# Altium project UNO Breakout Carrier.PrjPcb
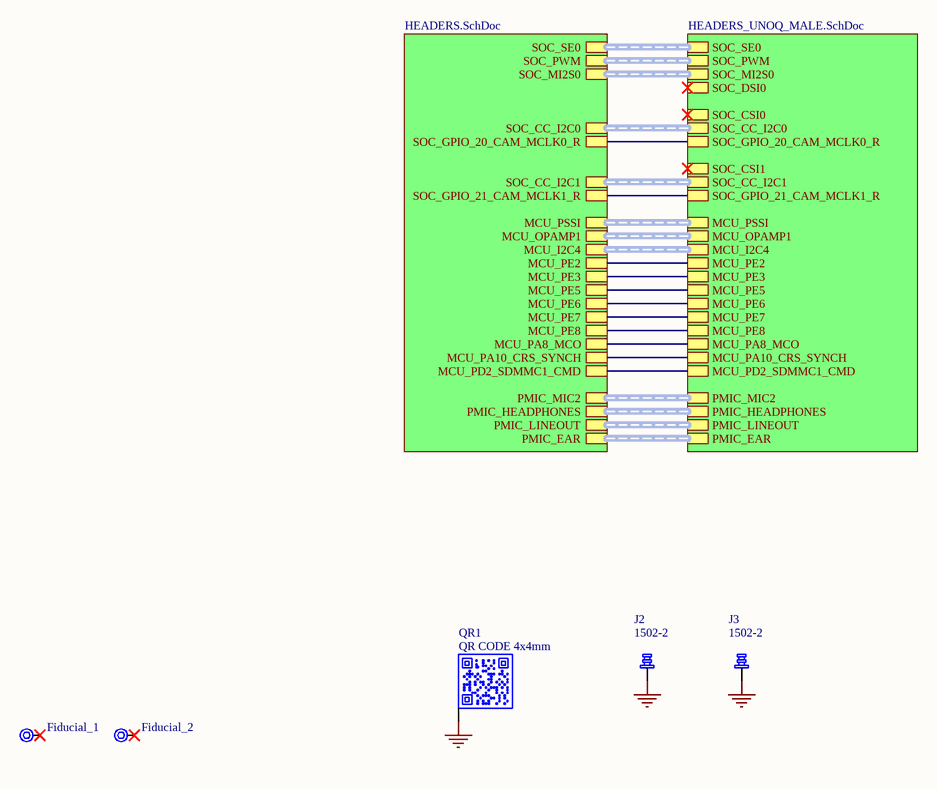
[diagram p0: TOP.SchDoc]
ADDITIONAL CODENAME: PANEN; ASSEMBLY_BGA: _; ASSEMBLY_PRESSFIT: _; ASSEMBLY_SMD: X; ASSEMBLY_THT: X; BOARD_CODENAME: UNO Breakout Carrier; BOARD_INFO_AUTHOR: Jonny Favaro; BOARD_INFO_AUTHOR_REV: Silvio Navaretti; BOARD_INFO_Er: _; BOARD_INFO_FLEX: _; BOARD_INFO_FR4: X; BOARD_INFO_FR4_HTG: _; BOARD_INFO_IPC1: _; BOARD_INFO_IPC2: X; BOARD_INFO_IPC3: _; BOARD_INFO_IPC_NA: _; BOARD_INFO_NUMBER_OF_LAYERS: 4; BOARD_INFO_PCB_SIZE: 107.6x53.34mm; BOARD_INFO_POLYMIDE: _; BOARD_INFO_RIGID: X; BOARD_INFO_RIGID/FLEX: _; BOARD_INFO_TBD: _; BOARD_INFO_THICKNESS: 1.6mm; DRILLS_BLIND: _; DRILLS_BURIED: _; DRILLS_COPPER_FILLING: _; DRILLS_FULL: X; DRILLS_LASER: _; DRILLS_PRESSFIT: _; DRILLS_RESIN_FILLING: _; DRILLS_SLOT: _; DRILLS_SOLDER_FILLING: X; FINISH_ADJUSTMENTS: _; FINISH_EDGE_PLATING: _; FINISH_ENIG: _; FINISH_HAL: _; FINISH_HAL_LF: X; FINISH_NI/AU: _; FINISH_SILK_BOTTOM: X; FINISH_SILK_COLOR: WHITE; FINISH_SILK_TOP: X; FINISH_SN/PB: _; FINISH_SOLDERMASK_BOTTOM: X; FINISH_SOLDERMASK_COLOR: BLUE; FINISH_SOLDERMASK_PEELABLE_BOTTOM: _; FINISH_SOLDERMASK_PEELABLE_COLOR: _; FINISH_SOLDERMASK_PEELABLE_TOP: _; FINISH_SOLDERMASK_TOP: X; FINISH_TABS: _; FINISH_TBD: _; INSULATION_MIN_INNER: 0.127mm; INSULATION_MIN_OUTER: 0.127mm; PANEL_MILLING: X; PANEL_NOT_REQUESTED: _; PANEL_NUMBER_OF_FIGURES: 5; PANEL_PROVIDED: X; PANEL_REQUESTED: _; PANEL_SCORING: X; PANEL_SIZE: 316.7x125.6mm; PANEL_TABS: _; SKU: ASX00085; TRACK_MIN_WIDTH_INNER: 0.127mm; TRACK_MIN_WIDTH_OUTER: 0.127mm; Version: V0.4; VIA_1: _; VIA_1_HOLE_MM: _; VIA_1_PAD_MM: _; VIA_2: _; VIA_2_HOLE_MM: _; VIA_2_PAD_MM: _; VIA_3: _; VIA_3_HOLE_MM: _; VIA_3_PAD_MM: _; VIA_4: _; VIA_4_HOLE_MM: _; VIA_4_PAD_MM: _; VIA_5: _; VIA_5_HOLE_MM: _; VIA_5_PAD_MM: _; VIA_THROUGH: X; VIA_THROUGH_HOLE_MM: 0.3; VIA_THROUGH_PAD_MM: 0.6
3 sheets, 10 parts. Net scope: hierarchical (ports join the sheet entries above them; power ports are global).
Board files: PCB.PcbDoc, PANEL.PcbDoc
Sheets:
  TOP.SchDoc
    U_HEADERS_IMOLA_MALE = HEADERS_UNOQ_MALE.SchDoc
    U_HEADERS = HEADERS.SchDoc

## Sheet TOP.SchDoc: TOP
size A4; Author: Jonny Favaro; CompanyName: ARDUINO SRL; Organization: ARDUINO SRL; SheetNumber: 1; SheetTotal: 3; RevAuthor: Jonny Favaro

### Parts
Fiducial_1  Fiducial mark 1mm with 2mm solder  [Fiducial mark 1mm with circle-Footprint-1]  (value not drawn)  (no BOM)
Fiducial_2  Fiducial mark 1mm with 2mm solder  [Fiducial mark 1mm with circle-Footprint-1]  (value not drawn)  (no BOM)
J2  1502-2  [1502-2]
J3  1502-2  [1502-2]
QR1  QR CODE 4x4mm  [QR CODE 4x4mm]  (no BOM)

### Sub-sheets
U_HEADERS = HEADERS.SchDoc: SOC_SE0, SOC_PWM, SOC_MI2S0, SOC_CC_I2C0, SOC_GPIO_20_CAM_MCLK0_R, SOC_CC_I2C1, SOC_GPIO_21_CAM_MCLK1_R, MCU_PSSI, MCU_OPAMP1, MCU_I2C4, MCU_PE2, MCU_PE3, MCU_PE5, MCU_PE6, MCU_PE7, MCU_PE8, MCU_PA8_MCO, MCU_PA10_CRS_SYNCH, MCU_PD2_SDMMC1_CMD, PMIC_MIC2, PMIC_HEADPHONES, PMIC_LINEOUT, PMIC_EAR
U_HEADERS_IMOLA_MALE = HEADERS_UNOQ_MALE.SchDoc: SOC_CSI0 (harness IMOLA_CSI), SOC_GPIO_20_CAM_MCLK0_R, SOC_CC_I2C1 (harness I2C), SOC_CSI1 (harness IMOLA_CSI), SOC_GPIO_21_CAM_MCLK1_R, SOC_CC_I2C0 (harness I2C), SOC_DSI0 (harness IMOLA_DSI), MCU_PSSI (harness PSSI_MCU), PMIC_MIC2 (harness MIC), MCU_PD2_SDMMC1_CMD, MCU_I2C4 (harness I2C), MCU_OPAMP1 (harness MCU_OPAMP), PMIC_LINEOUT (harness LINEOUT), PMIC_HEADPHONES (harness HEADPHONES), SOC_PWM (harness SOC_PWM), SOC_SE0 (harness SOC_GPIO), MCU_PA10_CRS_SYNCH, MCU_PA8_MCO, MCU_PE7, MCU_PE8, PMIC_EAR (harness EAT), SOC_MI2S0 (harness SOC_I2S), MCU_PE2, MCU_PE3, MCU_PE5, MCU_PE6

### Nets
GND: J2.1 J3.1 QR1.PAD
NetJ14_2: sheet U_HEADERS_IMOLA_MALE/SOC_GPIO_20_CAM_MCLK0_R, sheet U_HEADERS/SOC_GPIO_20_CAM_MCLK0_R
NetJ14_4: sheet U_HEADERS_IMOLA_MALE/SOC_GPIO_21_CAM_MCLK1_R, sheet U_HEADERS/SOC_GPIO_21_CAM_MCLK1_R
NetJ15_2: sheet U_HEADERS_IMOLA_MALE/MCU_PD2_SDMMC1_CMD, sheet U_HEADERS/MCU_PD2_SDMMC1_CMD
NetJ15_4: sheet U_HEADERS_IMOLA_MALE/MCU_PE2, sheet U_HEADERS/MCU_PE2
NetJ15_6: sheet U_HEADERS_IMOLA_MALE/MCU_PE3, sheet U_HEADERS/MCU_PE3
NetJ15_8: sheet U_HEADERS_IMOLA_MALE/MCU_PE5, sheet U_HEADERS/MCU_PE5
NetJ15_10: sheet U_HEADERS_IMOLA_MALE/MCU_PE6, sheet U_HEADERS/MCU_PE6
NetJ15_12: sheet U_HEADERS_IMOLA_MALE/MCU_PE7, sheet U_HEADERS/MCU_PE7
NetJ15_14: sheet U_HEADERS_IMOLA_MALE/MCU_PE8, sheet U_HEADERS/MCU_PE8
NetJ15_26: sheet U_HEADERS_IMOLA_MALE/MCU_PA8_MCO, sheet U_HEADERS/MCU_PA8_MCO
NetJ15_28: sheet U_HEADERS_IMOLA_MALE/MCU_PA10_CRS_SYNCH, sheet U_HEADERS/MCU_PA10_CRS_SYNCH

Not connected (* = marked no-connect by the designer): Fiducial_1 1*; Fiducial_2 1*

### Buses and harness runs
harness sheet U_HEADERS/MCU_I2C4 = sheet U_HEADERS_IMOLA_MALE/MCU_I2C4
harness sheet U_HEADERS/MCU_OPAMP1 = sheet U_HEADERS_IMOLA_MALE/MCU_OPAMP1
harness sheet U_HEADERS/MCU_PSSI = sheet U_HEADERS_IMOLA_MALE/MCU_PSSI
harness sheet U_HEADERS/PMIC_EAR = sheet U_HEADERS_IMOLA_MALE/PMIC_EAR
harness sheet U_HEADERS/PMIC_HEADPHONES = sheet U_HEADERS_IMOLA_MALE/PMIC_HEADPHONES
harness sheet U_HEADERS/PMIC_LINEOUT = sheet U_HEADERS_IMOLA_MALE/PMIC_LINEOUT
harness sheet U_HEADERS/PMIC_MIC2 = sheet U_HEADERS_IMOLA_MALE/PMIC_MIC2
harness sheet U_HEADERS/SOC_CC_I2C0 = sheet U_HEADERS_IMOLA_MALE/SOC_CC_I2C0
harness sheet U_HEADERS/SOC_CC_I2C1 = sheet U_HEADERS_IMOLA_MALE/SOC_CC_I2C1
harness sheet U_HEADERS/SOC_MI2S0 = sheet U_HEADERS_IMOLA_MALE/SOC_MI2S0
harness sheet U_HEADERS/SOC_PWM = sheet U_HEADERS_IMOLA_MALE/SOC_PWM
harness sheet U_HEADERS/SOC_SE0 = sheet U_HEADERS_IMOLA_MALE/SOC_SE0

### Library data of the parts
Fiducial_1 Fiducial_2 = UT0024-A.6
J2 J3 = J0379-A.2: Turret Connector TH 5,56mm lenght; Manufacturer: Keystone Electronics; Code Arduino: J0379
QR1 = QR-0001-A.5: QR CODE 4x4mm on layer 34 (This is not a component); Code Arduino: QRCODE_4x4mm

## Sheet HEADERS_UNOQ_MALE.SchDoc: HEADERS UNO Q MALE
size A3; Author: Jonny Favaro; CompanyName: Arduino SRL; Organization: Arduino SRL; SheetNumber: 2; SheetTotal: 3; RevAuthor: Jonny Favaro
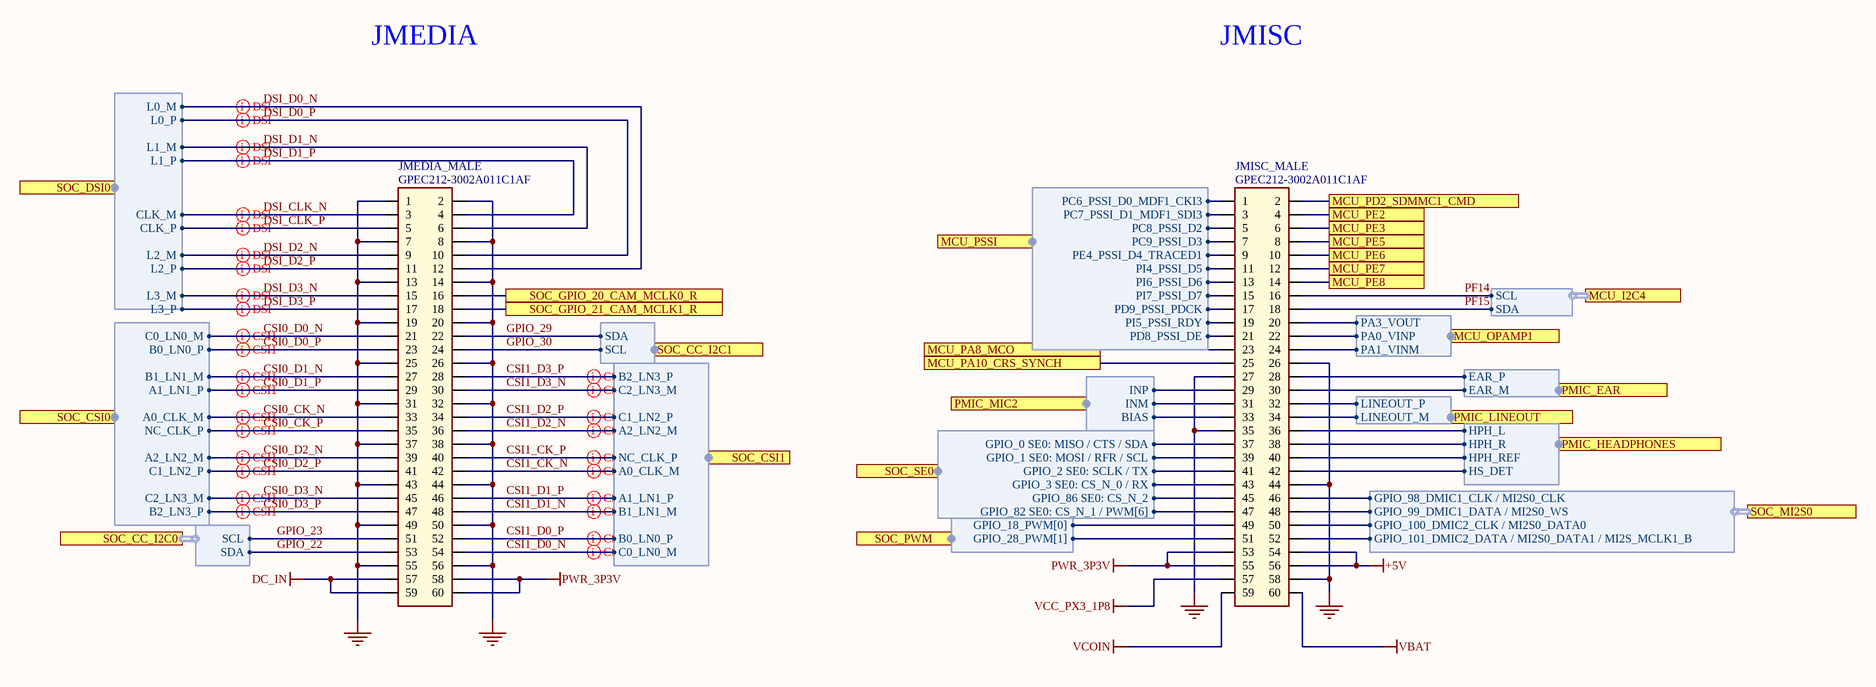
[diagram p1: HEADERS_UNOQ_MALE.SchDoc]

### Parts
JMEDIA_MALE  GPEC212-3002A011C1AF  [GPEC212-3002A011C1AF]
JMISC_MALE  GPEC212-3002A011C1AF  [GPEC212-3002A011C1AF]

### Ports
MCU_I2C4 (harness I2C), MCU_OPAMP1 (harness MCU_OPAMP), MCU_PA8_MCO, MCU_PA10_CRS_SYNCH, MCU_PD2_SDMMC1_CMD, MCU_PE2, MCU_PE3, MCU_PE5, MCU_PE6, MCU_PE7, MCU_PE8, MCU_PSSI (harness PSSI_MCU), PMIC_EAR (harness EAT), PMIC_HEADPHONES (harness HEADPHONES), PMIC_LINEOUT (harness LINEOUT), PMIC_MIC2 (harness MIC), SOC_CC_I2C0 (harness I2C), SOC_CC_I2C1 (harness I2C), SOC_CSI0 (harness IMOLA_CSI), SOC_CSI1 (harness IMOLA_CSI), SOC_DSI0 (harness IMOLA_DSI), SOC_GPIO_20_CAM_MCLK0_R, SOC_GPIO_21_CAM_MCLK1_R, SOC_MI2S0 (harness SOC_I2S), SOC_PWM (harness SOC_PWM), SOC_SE0 (harness SOC_GPIO)

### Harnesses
IMOLA_DSI: L1_P, L1_M, L3_P, L3_M, CLK_P, CLK_M, L0_P, L0_M, L2_P, L2_M
I2C: SDA, SCL
IMOLA_CSI: C2_LN3_M, A2_LN2_M, C1_LN2_P, C0_LN0_M, B0_LN0_P, A0_CLK_M, NC_CLK_P, B1_LN1_M, A1_LN1_P, B2_LN3_P
PSSI_MCU: PC6_PSSI_D0_MDF1_CKI3, PC7_PSSI_D1_MDF1_SDI3, PC8_PSSI_D2, PC9_PSSI_D3, PE4_PSSI_D4_TRACED1, PI4_PSSI_D5, PI6_PSSI_D6, PI7_PSSI_D7, PD9_PSSI_PDCK, PI5_PSSI_RDY, PD8_PSSI_DE
MCU_OPAMP: PA3_VOUT, PA0_VINP, PA1_VINM
EAT: EAR_P, EAR_M
MIC: INP, INM, BIAS
LINEOUT: LINEOUT_P, LINEOUT_M
HEADPHONES: HPH_L, HPH_R, HPH_REF, HS_DET
SOC_GPIO: GPIO_0 SE0: MISO / CTS / SDA, GPIO_1 SE0: MOSI / RFR / SCL, GPIO_2 SE0: SCLK / TX, GPIO_3 SE0: CS_N_0 / RX, GPIO_86 SE0: CS_N_2, GPIO_82 SE0: CS_N_1 / PWM[6]
SOC_I2S: GPIO_98_DMIC1_CLK / MI2S0_CLK, GPIO_99_DMIC1_DATA / MI2S0_WS, GPIO_100_DMIC2_CLK / MI2S0_DATA0, GPIO_101_DMIC2_DATA / MI2S0_DATA1 / MI2S_MCLK1_B
SOC_PWM: GPIO_18_PWM[0], GPIO_28_PWM[1]

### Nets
+5V: JMISC_MALE.54 JMISC_MALE.56
DC_IN: JMEDIA_MALE.57 JMEDIA_MALE.59
GND: JMEDIA_MALE.1 JMEDIA_MALE.2 JMEDIA_MALE.7 JMEDIA_MALE.8 JMEDIA_MALE.13 JMEDIA_MALE.14 JMEDIA_MALE.19 JMEDIA_MALE.20 JMEDIA_MALE.25 JMEDIA_MALE.26 JMEDIA_MALE.31 JMEDIA_MALE.32 JMEDIA_MALE.37 JMEDIA_MALE.38 JMEDIA_MALE.43 JMEDIA_MALE.44 JMEDIA_MALE.49 JMEDIA_MALE.50 JMEDIA_MALE.55 JMEDIA_MALE.56 JMISC_MALE.26 JMISC_MALE.27 JMISC_MALE.35 JMISC_MALE.44 JMISC_MALE.58
PWR_3P3V: JMEDIA_MALE.58 JMEDIA_MALE.60 JMISC_MALE.53 JMISC_MALE.55
VBAT: JMISC_MALE.60
VCC_PX3_1P8: JMISC_MALE.57
VCOIN: JMISC_MALE.59
CSI0_CK_N: JMEDIA_MALE.33 ; port SOC_CSI0.A0_CLK_M
CSI0_CK_P: JMEDIA_MALE.35 ; port SOC_CSI0.NC_CLK_P
CSI0_D0_N: JMEDIA_MALE.21 ; port SOC_CSI0.C0_LN0_M
CSI0_D0_P: JMEDIA_MALE.23 ; port SOC_CSI0.B0_LN0_P
CSI0_D1_N: JMEDIA_MALE.27 ; port SOC_CSI0.B1_LN1_M
CSI0_D1_P: JMEDIA_MALE.29 ; port SOC_CSI0.A1_LN1_P
CSI0_D2_N: JMEDIA_MALE.39 ; port SOC_CSI0.A2_LN2_M
CSI0_D2_P: JMEDIA_MALE.41 ; port SOC_CSI0.C1_LN2_P
CSI0_D3_N: JMEDIA_MALE.45 ; port SOC_CSI0.C2_LN3_M
CSI0_D3_P: JMEDIA_MALE.47 ; port SOC_CSI0.B2_LN3_P
CSI1_CK_N: JMEDIA_MALE.42 ; port SOC_CSI1.A0_CLK_M
CSI1_CK_P: JMEDIA_MALE.40 ; port SOC_CSI1.NC_CLK_P
CSI1_D0_N: JMEDIA_MALE.54 ; port SOC_CSI1.C0_LN0_M
CSI1_D0_P: JMEDIA_MALE.52 ; port SOC_CSI1.B0_LN0_P
CSI1_D1_N: JMEDIA_MALE.48 ; port SOC_CSI1.B1_LN1_M
CSI1_D1_P: JMEDIA_MALE.46 ; port SOC_CSI1.A1_LN1_P
CSI1_D2_N: JMEDIA_MALE.36 ; port SOC_CSI1.A2_LN2_M
CSI1_D2_P: JMEDIA_MALE.34 ; port SOC_CSI1.C1_LN2_P
CSI1_D3_N: JMEDIA_MALE.30 ; port SOC_CSI1.C2_LN3_M
CSI1_D3_P: JMEDIA_MALE.28 ; port SOC_CSI1.B2_LN3_P
DSI_CLK_N: JMEDIA_MALE.3 ; port SOC_DSI0.CLK_M
DSI_CLK_P: JMEDIA_MALE.5 ; port SOC_DSI0.CLK_P
DSI_D0_N: JMEDIA_MALE.12 ; port SOC_DSI0.L0_M
DSI_D0_P: JMEDIA_MALE.10 ; port SOC_DSI0.L0_P
DSI_D1_N: JMEDIA_MALE.6 ; port SOC_DSI0.L1_M
DSI_D1_P: JMEDIA_MALE.4 ; port SOC_DSI0.L1_P
DSI_D2_N: JMEDIA_MALE.9 ; port SOC_DSI0.L2_M
DSI_D2_P: JMEDIA_MALE.11 ; port SOC_DSI0.L2_P
DSI_D3_N: JMEDIA_MALE.15 ; port SOC_DSI0.L3_M
DSI_D3_P: JMEDIA_MALE.17 ; port SOC_DSI0.L3_P
GPIO_22: JMEDIA_MALE.53 ; port SOC_CC_I2C0.SDA
GPIO_23: JMEDIA_MALE.51 ; port SOC_CC_I2C0.SCL
GPIO_29: JMEDIA_MALE.22 ; port SOC_CC_I2C1.SDA
GPIO_30: JMEDIA_MALE.24 ; port SOC_CC_I2C1.SCL
PF14: JMISC_MALE.16 ; port MCU_I2C4.SCL
PF15: JMISC_MALE.18 ; port MCU_I2C4.SDA
NetJ14_2: JMEDIA_MALE.16 ; port SOC_GPIO_20_CAM_MCLK0_R
NetJ14_4: JMEDIA_MALE.18 ; port SOC_GPIO_21_CAM_MCLK1_R
NetJ14_20: JMISC_MALE.29 ; port PMIC_MIC2.INP
NetJ14_22: JMISC_MALE.31 ; port PMIC_MIC2.INM
NetJ14_24: JMISC_MALE.33 ; port PMIC_MIC2.BIAS
NetJ14_27: JMISC_MALE.32 ; port PMIC_LINEOUT.LINEOUT_P
NetJ14_28: JMISC_MALE.28 ; port PMIC_EAR.EAR_P
NetJ14_29: JMISC_MALE.34 ; port PMIC_LINEOUT.LINEOUT_M
NetJ14_30: JMISC_MALE.30 ; port PMIC_EAR.EAR_M
NetJ14_34: JMISC_MALE.36 ; port PMIC_HEADPHONES.HPH_L
NetJ14_36: JMISC_MALE.38 ; port PMIC_HEADPHONES.HPH_R
NetJ14_38: JMISC_MALE.40 ; port PMIC_HEADPHONES.HPH_REF
NetJ14_40: JMISC_MALE.42 ; port PMIC_HEADPHONES.HS_DET
NetJ15_1: JMISC_MALE.1 ; port MCU_PSSI.PC6_PSSI_D0_MDF1_CKI3
NetJ15_2: JMISC_MALE.2 ; port MCU_PD2_SDMMC1_CMD
NetJ15_3: JMISC_MALE.3 ; port MCU_PSSI.PC7_PSSI_D1_MDF1_SDI3
NetJ15_4: JMISC_MALE.4 ; port MCU_PE2
NetJ15_5: JMISC_MALE.5 ; port MCU_PSSI.PC8_PSSI_D2
NetJ15_6: JMISC_MALE.6 ; port MCU_PE3
NetJ15_7: JMISC_MALE.7 ; port MCU_PSSI.PC9_PSSI_D3
NetJ15_8: JMISC_MALE.8 ; port MCU_PE5
NetJ15_9: JMISC_MALE.9 ; port MCU_PSSI.PE4_PSSI_D4_TRACED1
NetJ15_10: JMISC_MALE.10 ; port MCU_PE6
NetJ15_11: JMISC_MALE.11 ; port MCU_PSSI.PI4_PSSI_D5
NetJ15_12: JMISC_MALE.12 ; port MCU_PE7
NetJ15_13: JMISC_MALE.13 ; port MCU_PSSI.PI6_PSSI_D6
NetJ15_14: JMISC_MALE.14 ; port MCU_PE8
NetJ15_15: JMISC_MALE.15 ; port MCU_PSSI.PI7_PSSI_D7
NetJ15_17: JMISC_MALE.17 ; port MCU_PSSI.PD9_PSSI_PDCK
NetJ15_19: JMISC_MALE.19 ; port MCU_PSSI.PI5_PSSI_RDY
NetJ15_20: JMISC_MALE.20 ; port MCU_OPAMP1.PA3_VOUT
NetJ15_21: JMISC_MALE.21 ; port MCU_PSSI.PD8_PSSI_DE
NetJ15_22: JMISC_MALE.22 ; port MCU_OPAMP1.PA0_VINP
NetJ15_24: JMISC_MALE.24 ; port MCU_OPAMP1.PA1_VINM
NetJ15_25: JMISC_MALE.37 ; port SOC_SE0.GPIO_0 SE0: MISO / CTS / SDA
NetJ15_26: JMISC_MALE.23 ; port MCU_PA8_MCO
NetJ15_27: JMISC_MALE.39 ; port SOC_SE0.GPIO_1 SE0: MOSI / RFR / SCL
NetJ15_28: JMISC_MALE.25 ; port MCU_PA10_CRS_SYNCH
NetJ15_29: JMISC_MALE.41 ; port SOC_SE0.GPIO_2 SE0: SCLK / TX
NetJ15_31: JMISC_MALE.43 ; port SOC_SE0.GPIO_3 SE0: CS_N_0 / RX
NetJ15_32: JMISC_MALE.46 ; port SOC_MI2S0.GPIO_98_DMIC1_CLK / MI2S0_CLK
NetJ15_33: JMISC_MALE.45 ; port SOC_SE0.GPIO_86 SE0: CS_N_2
NetJ15_34: JMISC_MALE.48 ; port SOC_MI2S0.GPIO_99_DMIC1_DATA / MI2S0_WS
NetJ15_35: JMISC_MALE.47 ; port SOC_SE0.GPIO_82 SE0: CS_N_1 / PWM[6]
NetJ15_36: JMISC_MALE.50 ; port SOC_MI2S0.GPIO_100_DMIC2_CLK / MI2S0_DATA0
NetJ15_37: JMISC_MALE.49 ; port SOC_PWM.GPIO_18_PWM[0]
NetJ15_38: JMISC_MALE.52 ; port SOC_MI2S0.GPIO_101_DMIC2_DATA / MI2S0_DATA1 / MI2S_MCLK1_B
NetJ15_39: JMISC_MALE.51 ; port SOC_PWM.GPIO_28_PWM[1]

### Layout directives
differential pair; differential pair class DSI; net class IMPEDANCE_100R: DSI_CLK_N, DSI_CLK_P, DSI_D0_N, DSI_D0_P, DSI_D1_N, DSI_D1_P, DSI_D2_N, DSI_D2_P, DSI_D3_N, DSI_D3_P
differential pair; differential pair class CSI1; net class IMPEDANCE_100R: CSI0_CK_N, CSI0_CK_P, CSI0_D0_N, CSI0_D0_P, CSI0_D1_N, CSI0_D1_P, CSI0_D2_N, CSI0_D2_P, CSI0_D3_N, CSI0_D3_P
differential pair; differential pair class CSI0; net class IMPEDANCE_100R: CSI1_CK_N, CSI1_CK_P, CSI1_D0_N, CSI1_D0_P, CSI1_D1_N, CSI1_D1_P, CSI1_D2_N, CSI1_D2_P, CSI1_D3_N, CSI1_D3_P

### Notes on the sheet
- JMEDIA
- JMISC

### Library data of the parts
JMEDIA_MALE JMISC_MALE = J0568-A.3: CONN HEADER MALE VERTICAL SMD 1.27mm 2x30 POS lead heigth 3.5mm; Manufacturer: Greenconn; Code Arduino: J0568

## Sheet HEADERS.SchDoc: HEADERS
size A4; Author: Jonny Favaro; CompanyName: Arduino srl; Organization: ARDUINO SRL; SheetNumber: 3; SheetTotal: 3; RevAuthor: Jonny Favaro
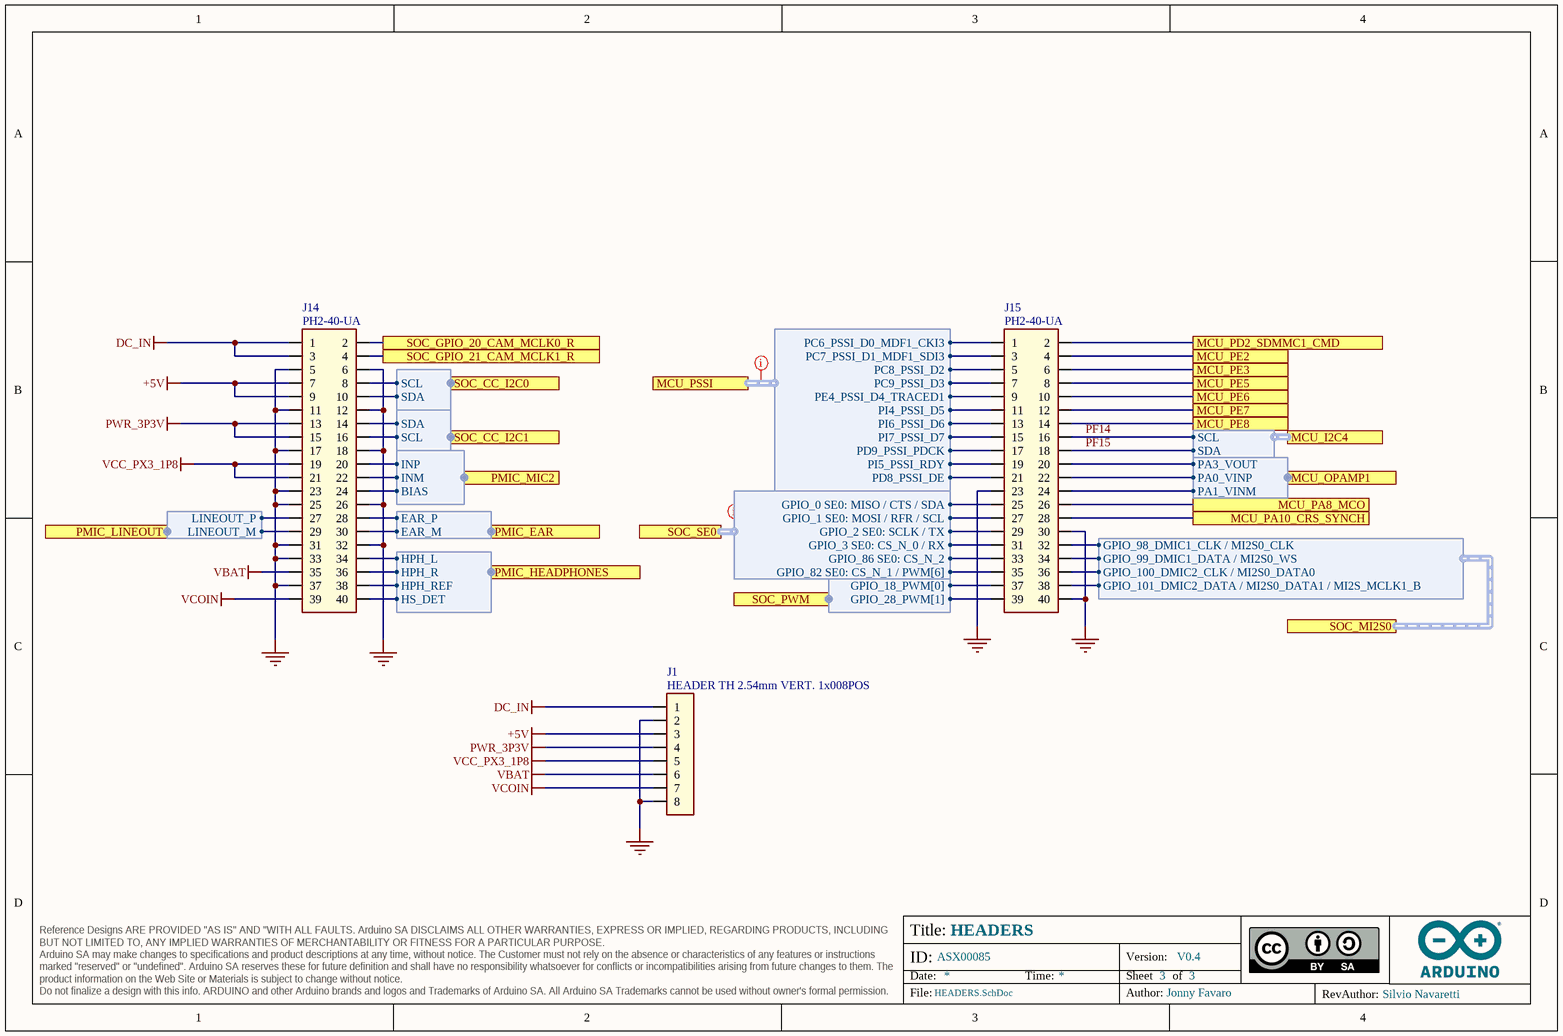
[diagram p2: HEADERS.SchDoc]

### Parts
J1  HEADER TH 2.54mm VERT. 1x008POS  [PIN HEADER 2.54mm VERT. 1x8POS]  (no BOM)
J14  PH2-40-UA  [PIN HEADER 2.54mm VERT. 2x20POS]
J15  PH2-40-UA  [PIN HEADER 2.54mm VERT. 2x20POS]

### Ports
MCU_I2C4 (harness I2C), MCU_OPAMP1 (harness MCU_OPAMP), MCU_PA8_MCO, MCU_PA10_CRS_SYNCH, MCU_PD2_SDMMC1_CMD, MCU_PE2, MCU_PE3, MCU_PE5, MCU_PE6, MCU_PE7, MCU_PE8, MCU_PSSI (harness PSSI_MCU), PMIC_EAR (harness EAT), PMIC_HEADPHONES (harness HEADPHONES), PMIC_LINEOUT (harness LINEOUT), PMIC_MIC2 (harness MIC), SOC_CC_I2C0 (harness I2C), SOC_CC_I2C1 (harness I2C), SOC_GPIO_20_CAM_MCLK0_R, SOC_GPIO_21_CAM_MCLK1_R, SOC_MI2S0 (harness SOC_I2S), SOC_PWM (harness SOC_PWM), SOC_SE0 (harness SOC_GPIO)

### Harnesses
SOC_GPIO: GPIO_0 SE0: MISO / CTS / SDA, GPIO_1 SE0: MOSI / RFR / SCL, GPIO_2 SE0: SCLK / TX, GPIO_3 SE0: CS_N_0 / RX, GPIO_86 SE0: CS_N_2, GPIO_82 SE0: CS_N_1 / PWM[6]
SOC_PWM: GPIO_18_PWM[0], GPIO_28_PWM[1]
I2C: SDA, SCL
MCU_OPAMP: PA3_VOUT, PA0_VINP, PA1_VINM
SOC_I2S: GPIO_98_DMIC1_CLK / MI2S0_CLK, GPIO_99_DMIC1_DATA / MI2S0_WS, GPIO_100_DMIC2_CLK / MI2S0_DATA0, GPIO_101_DMIC2_DATA / MI2S0_DATA1 / MI2S_MCLK1_B
PSSI_MCU: PC6_PSSI_D0_MDF1_CKI3, PC7_PSSI_D1_MDF1_SDI3, PC8_PSSI_D2, PC9_PSSI_D3, PE4_PSSI_D4_TRACED1, PI4_PSSI_D5, PI6_PSSI_D6, PI7_PSSI_D7, PD9_PSSI_PDCK, PI5_PSSI_RDY, PD8_PSSI_DE
HEADPHONES: HPH_L, HPH_R, HPH_REF, HS_DET
MIC: INP, INM, BIAS
EAT: EAR_P, EAR_M
LINEOUT: LINEOUT_P, LINEOUT_M

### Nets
+5V: J1.3 J14.7 J14.9
DC_IN: J1.1 J14.1 J14.3
GND: J1.2 J1.8 J14.5 J14.6 J14.11 J14.12 J14.17 J14.18 J14.23 J14.25 J14.26 J14.31 J14.32 J14.33 J14.37 J15.23 J15.30 J15.40
PWR_3P3V: J1.4 J14.13 J14.15
VBAT: J1.6 J14.35
VCC_PX3_1P8: J1.5 J14.19 J14.21
VCOIN: J1.7 J14.39
GPIO_22: J14.10 ; port SOC_CC_I2C0.SDA
GPIO_23: J14.8 ; port SOC_CC_I2C0.SCL
GPIO_29: J14.14 ; port SOC_CC_I2C1.SDA
GPIO_30: J14.16 ; port SOC_CC_I2C1.SCL
PF14: J15.16 ; port MCU_I2C4.SCL
PF15: J15.18 ; port MCU_I2C4.SDA
NetJ14_2: J14.2 ; port SOC_GPIO_20_CAM_MCLK0_R
NetJ14_4: J14.4 ; port SOC_GPIO_21_CAM_MCLK1_R
NetJ14_20: J14.20 ; port PMIC_MIC2.INP
NetJ14_22: J14.22 ; port PMIC_MIC2.INM
NetJ14_24: J14.24 ; port PMIC_MIC2.BIAS
NetJ14_27: J14.27 ; port PMIC_LINEOUT.LINEOUT_P
NetJ14_28: J14.28 ; port PMIC_EAR.EAR_P
NetJ14_29: J14.29 ; port PMIC_LINEOUT.LINEOUT_M
NetJ14_30: J14.30 ; port PMIC_EAR.EAR_M
NetJ14_34: J14.34 ; port PMIC_HEADPHONES.HPH_L
NetJ14_36: J14.36 ; port PMIC_HEADPHONES.HPH_R
NetJ14_38: J14.38 ; port PMIC_HEADPHONES.HPH_REF
NetJ14_40: J14.40 ; port PMIC_HEADPHONES.HS_DET
NetJ15_1: J15.1 ; port MCU_PSSI.PC6_PSSI_D0_MDF1_CKI3
NetJ15_2: J15.2 ; port MCU_PD2_SDMMC1_CMD
NetJ15_3: J15.3 ; port MCU_PSSI.PC7_PSSI_D1_MDF1_SDI3
NetJ15_4: J15.4 ; port MCU_PE2
NetJ15_5: J15.5 ; port MCU_PSSI.PC8_PSSI_D2
NetJ15_6: J15.6 ; port MCU_PE3
NetJ15_7: J15.7 ; port MCU_PSSI.PC9_PSSI_D3
NetJ15_8: J15.8 ; port MCU_PE5
NetJ15_9: J15.9 ; port MCU_PSSI.PE4_PSSI_D4_TRACED1
NetJ15_10: J15.10 ; port MCU_PE6
NetJ15_11: J15.11 ; port MCU_PSSI.PI4_PSSI_D5
NetJ15_12: J15.12 ; port MCU_PE7
NetJ15_13: J15.13 ; port MCU_PSSI.PI6_PSSI_D6
NetJ15_14: J15.14 ; port MCU_PE8
NetJ15_15: J15.15 ; port MCU_PSSI.PI7_PSSI_D7
NetJ15_17: J15.17 ; port MCU_PSSI.PD9_PSSI_PDCK
NetJ15_19: J15.19 ; port MCU_PSSI.PI5_PSSI_RDY
NetJ15_20: J15.20 ; port MCU_OPAMP1.PA3_VOUT
NetJ15_21: J15.21 ; port MCU_PSSI.PD8_PSSI_DE
NetJ15_22: J15.22 ; port MCU_OPAMP1.PA0_VINP
NetJ15_24: J15.24 ; port MCU_OPAMP1.PA1_VINM
NetJ15_25: J15.25 ; port SOC_SE0.GPIO_0 SE0: MISO / CTS / SDA
NetJ15_26: J15.26 ; port MCU_PA8_MCO
NetJ15_27: J15.27 ; port SOC_SE0.GPIO_1 SE0: MOSI / RFR / SCL
NetJ15_28: J15.28 ; port MCU_PA10_CRS_SYNCH
NetJ15_29: J15.29 ; port SOC_SE0.GPIO_2 SE0: SCLK / TX
NetJ15_31: J15.31 ; port SOC_SE0.GPIO_3 SE0: CS_N_0 / RX
NetJ15_32: J15.32 ; port SOC_MI2S0.GPIO_98_DMIC1_CLK / MI2S0_CLK
NetJ15_33: J15.33 ; port SOC_SE0.GPIO_86 SE0: CS_N_2
NetJ15_34: J15.34 ; port SOC_MI2S0.GPIO_99_DMIC1_DATA / MI2S0_WS
NetJ15_35: J15.35 ; port SOC_SE0.GPIO_82 SE0: CS_N_1 / PWM[6]
NetJ15_36: J15.36 ; port SOC_MI2S0.GPIO_100_DMIC2_CLK / MI2S0_DATA0
NetJ15_37: J15.37 ; port SOC_PWM.GPIO_18_PWM[0]
NetJ15_38: J15.38 ; port SOC_MI2S0.GPIO_101_DMIC2_DATA / MI2S0_DATA1 / MI2S_MCLK1_B
NetJ15_39: J15.39 ; port SOC_PWM.GPIO_28_PWM[1]

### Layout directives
net class PSSI_Lines: (no net found under the mark)
net class SE0_Lines: (no net found under the mark)

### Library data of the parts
J1 = J0171-A.4: Code Arduino: J0171
J14 J15 = J0326-A.4: HEADER TH 2.54mm VERT. MALE 2x20POS; Manufacturer: Adam Tech; Code Arduino: J0326

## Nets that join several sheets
+5V: HEADERS_UNOQ_MALE (JMISC_MALE.54 JMISC_MALE.56), HEADERS (J1.3 J14.7 J14.9)
DC_IN: HEADERS_UNOQ_MALE (JMEDIA_MALE.57 JMEDIA_MALE.59), HEADERS (J1.1 J14.1 J14.3)
GND: TOP (J2.1 J3.1 QR1.PAD), HEADERS_UNOQ_MALE (25 pins), HEADERS (18 pins)
PWR_3P3V: HEADERS_UNOQ_MALE (JMEDIA_MALE.58 JMEDIA_MALE.60 JMISC_MALE.53 JMISC_MALE.55), HEADERS (J1.4 J14.13 J14.15)
VBAT: HEADERS_UNOQ_MALE (JMISC_MALE.60), HEADERS (J1.6 J14.35)
VCC_PX3_1P8: HEADERS_UNOQ_MALE (JMISC_MALE.57), HEADERS (J1.5 J14.19 J14.21)
VCOIN: HEADERS_UNOQ_MALE (JMISC_MALE.59), HEADERS (J1.7 J14.39)
GPIO_22: HEADERS_UNOQ_MALE (JMEDIA_MALE.53), HEADERS (J14.10)
GPIO_23: HEADERS_UNOQ_MALE (JMEDIA_MALE.51), HEADERS (J14.8)
GPIO_29: HEADERS_UNOQ_MALE (JMEDIA_MALE.22), HEADERS (J14.14)
GPIO_30: HEADERS_UNOQ_MALE (JMEDIA_MALE.24), HEADERS (J14.16)
NetJ14_2: HEADERS_UNOQ_MALE (JMEDIA_MALE.16), HEADERS (J14.2)
NetJ14_4: HEADERS_UNOQ_MALE (JMEDIA_MALE.18), HEADERS (J14.4)
NetJ14_20: HEADERS_UNOQ_MALE (JMISC_MALE.29), HEADERS (J14.20)
NetJ14_22: HEADERS_UNOQ_MALE (JMISC_MALE.31), HEADERS (J14.22)
NetJ14_24: HEADERS_UNOQ_MALE (JMISC_MALE.33), HEADERS (J14.24)
NetJ14_27: HEADERS_UNOQ_MALE (JMISC_MALE.32), HEADERS (J14.27)
NetJ14_28: HEADERS_UNOQ_MALE (JMISC_MALE.28), HEADERS (J14.28)
NetJ14_29: HEADERS_UNOQ_MALE (JMISC_MALE.34), HEADERS (J14.29)
NetJ14_30: HEADERS_UNOQ_MALE (JMISC_MALE.30), HEADERS (J14.30)
NetJ14_34: HEADERS_UNOQ_MALE (JMISC_MALE.36), HEADERS (J14.34)
NetJ14_36: HEADERS_UNOQ_MALE (JMISC_MALE.38), HEADERS (J14.36)
NetJ14_38: HEADERS_UNOQ_MALE (JMISC_MALE.40), HEADERS (J14.38)
NetJ14_40: HEADERS_UNOQ_MALE (JMISC_MALE.42), HEADERS (J14.40)
NetJ15_1: HEADERS_UNOQ_MALE (JMISC_MALE.1), HEADERS (J15.1)
NetJ15_2: HEADERS_UNOQ_MALE (JMISC_MALE.2), HEADERS (J15.2)
NetJ15_3: HEADERS_UNOQ_MALE (JMISC_MALE.3), HEADERS (J15.3)
NetJ15_4: HEADERS_UNOQ_MALE (JMISC_MALE.4), HEADERS (J15.4)
NetJ15_5: HEADERS_UNOQ_MALE (JMISC_MALE.5), HEADERS (J15.5)
NetJ15_6: HEADERS_UNOQ_MALE (JMISC_MALE.6), HEADERS (J15.6)
NetJ15_7: HEADERS_UNOQ_MALE (JMISC_MALE.7), HEADERS (J15.7)
NetJ15_8: HEADERS_UNOQ_MALE (JMISC_MALE.8), HEADERS (J15.8)
NetJ15_9: HEADERS_UNOQ_MALE (JMISC_MALE.9), HEADERS (J15.9)
NetJ15_10: HEADERS_UNOQ_MALE (JMISC_MALE.10), HEADERS (J15.10)
NetJ15_11: HEADERS_UNOQ_MALE (JMISC_MALE.11), HEADERS (J15.11)
NetJ15_12: HEADERS_UNOQ_MALE (JMISC_MALE.12), HEADERS (J15.12)
NetJ15_13: HEADERS_UNOQ_MALE (JMISC_MALE.13), HEADERS (J15.13)
NetJ15_14: HEADERS_UNOQ_MALE (JMISC_MALE.14), HEADERS (J15.14)
NetJ15_15: HEADERS_UNOQ_MALE (JMISC_MALE.15), HEADERS (J15.15)
NetJ15_17: HEADERS_UNOQ_MALE (JMISC_MALE.17), HEADERS (J15.17)
NetJ15_19: HEADERS_UNOQ_MALE (JMISC_MALE.19), HEADERS (J15.19)
NetJ15_20: HEADERS_UNOQ_MALE (JMISC_MALE.20), HEADERS (J15.20)
NetJ15_21: HEADERS_UNOQ_MALE (JMISC_MALE.21), HEADERS (J15.21)
NetJ15_22: HEADERS_UNOQ_MALE (JMISC_MALE.22), HEADERS (J15.22)
NetJ15_24: HEADERS_UNOQ_MALE (JMISC_MALE.24), HEADERS (J15.24)
NetJ15_25: HEADERS_UNOQ_MALE (JMISC_MALE.37), HEADERS (J15.25)
NetJ15_26: HEADERS_UNOQ_MALE (JMISC_MALE.23), HEADERS (J15.26)
NetJ15_27: HEADERS_UNOQ_MALE (JMISC_MALE.39), HEADERS (J15.27)
NetJ15_28: HEADERS_UNOQ_MALE (JMISC_MALE.25), HEADERS (J15.28)
NetJ15_29: HEADERS_UNOQ_MALE (JMISC_MALE.41), HEADERS (J15.29)
NetJ15_31: HEADERS_UNOQ_MALE (JMISC_MALE.43), HEADERS (J15.31)
NetJ15_32: HEADERS_UNOQ_MALE (JMISC_MALE.46), HEADERS (J15.32)
NetJ15_33: HEADERS_UNOQ_MALE (JMISC_MALE.45), HEADERS (J15.33)
NetJ15_34: HEADERS_UNOQ_MALE (JMISC_MALE.48), HEADERS (J15.34)
NetJ15_35: HEADERS_UNOQ_MALE (JMISC_MALE.47), HEADERS (J15.35)
NetJ15_36: HEADERS_UNOQ_MALE (JMISC_MALE.50), HEADERS (J15.36)
NetJ15_37: HEADERS_UNOQ_MALE (JMISC_MALE.49), HEADERS (J15.37)
NetJ15_38: HEADERS_UNOQ_MALE (JMISC_MALE.52), HEADERS (J15.38)
NetJ15_39: HEADERS_UNOQ_MALE (JMISC_MALE.51), HEADERS (J15.39)
PF14: HEADERS_UNOQ_MALE (JMISC_MALE.16), HEADERS (J15.16)
PF15: HEADERS_UNOQ_MALE (JMISC_MALE.18), HEADERS (J15.18)

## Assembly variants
ASX00085: all parts fitted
